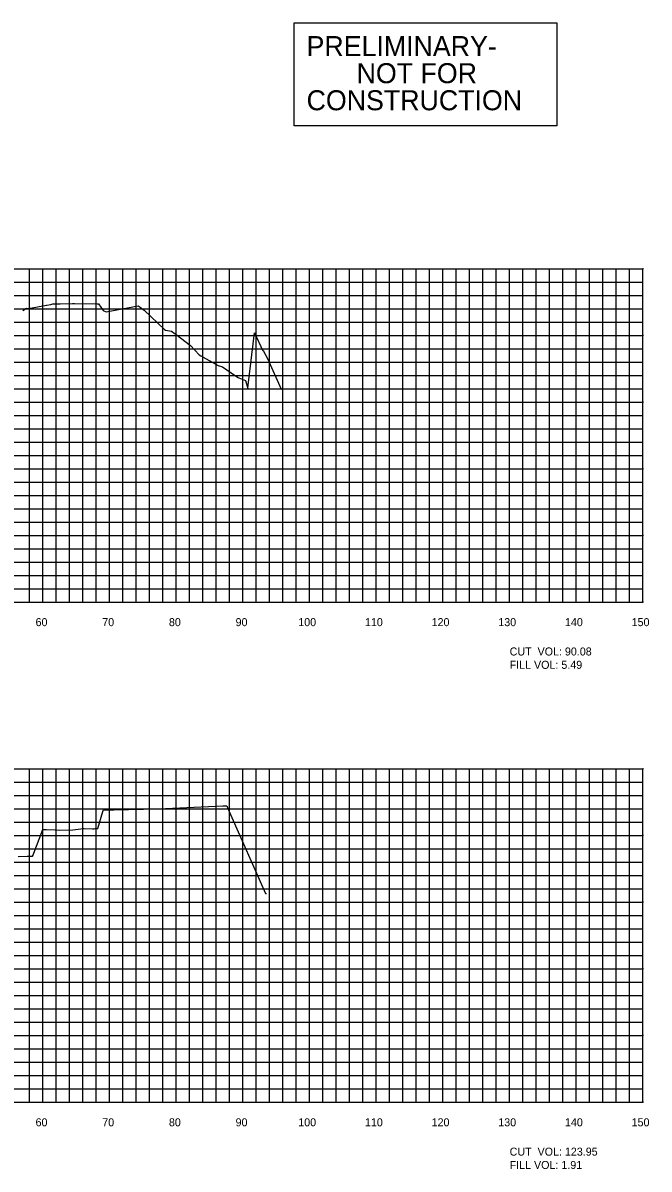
# Model space of a CAD drawing. Extents: x 1800880 to 1814006, y 250083 to 250560.
# Drawn here: x 1813568 to 1813661.9, y 250089.4 to 250261.3 of the extents above; entities that cross this region are included whole.
import ezdxf

# ---------------------------------------------------------------- set-up
doc = ezdxf.new("R2010")
doc.units = 0
for name, color, linetype in [('CL-CNST', 7, 'Continuous'), ('DESIGN - DRAINAGE - Bridges', 7, 'Continuous'), ('DRAINAGETXT', 7, 'Continuous'), ('Level 32', 7, 'Continuous'), ('Level 46', 7, 'Continuous')]:
    doc.layers.add(name, color=color, linetype=linetype)

msp = doc.modelspace()

# ---------------------------------------------------------------- linework, layer by layer
at = {"layer": 'CL-CNST'}
for points in [[(1813567.99, 250218.16), (1813568.52, 250218.53), (1813568.83, 250218.48), (1813571.52, 250218.96), (1813571.59, 250218.97), (1813572.13, 250219.04), (1813572.19, 250219.05), (1813572.5, 250219.14), (1813572.64, 250219.17), (1813572.67, 250219.17), (1813572.71, 250219.17), (1813573.05, 250219.17), (1813573.19, 250219.17), (1813573.61, 250219.18), (1813575.42, 250219.23), (1813575.72, 250219.23), (1813579.16, 250219.18), (1813579.32, 250219.18), (1813580.05, 250218.15), (1813580.48, 250217.94), (1813585.27, 250218.88), (1813585.61, 250218.64), (1813586.2, 250218.22), (1813589.23, 250215.33), (1813589.38, 250215.23), (1813590.29, 250215.04), (1813590.47, 250214.9), (1813590.63, 250214.79), (1813590.97, 250214.55), (1813593.14, 250212.93), (1813594.44, 250211.51), (1813594.68, 250211.36), (1813595.02, 250211.14), (1813597.27, 250209.91), (1813597.95, 250209.71), (1813599.87, 250208.39), (1813600.3, 250208.1), (1813600.38, 250208.05), (1813601.38, 250207.66), (1813601.64, 250206.84), (1813601.72, 250206.46), (1813601.8, 250206.96), (1813602.74, 250214.82), (1813603.99, 250212.11), (1813604.03, 250212.18), (1813604.7, 250210.98), (1813606.73, 250206.35), (1813607.05, 250206.41)], [(1813567.29, 250136.3), (1813568.62, 250136.36), (1813568.62, 250136.36), (1813568.63, 250136.36), (1813569.06, 250136.36), (1813569.43, 250136.36), (1813569.46, 250136.36), (1813569.52, 250136.5), (1813569.55, 250136.54), (1813569.64, 250136.8), (1813570.44, 250138.91), (1813570.99, 250140.35), (1813571.45, 250140.34), (1813571.53, 250140.34), (1813572.84, 250140.28), (1813573.56, 250140.25), (1813575.51, 250140.29), (1813577.08, 250140.49), (1813577.21, 250140.49), (1813578.46, 250140.46), (1813578.71, 250140.46), (1813578.82, 250140.47), (1813579.24, 250140.48), (1813580.01, 250143.02), (1813580.1, 250143.29), (1813580.34, 250143.29), (1813580.38, 250143.29), (1813580.63, 250143.29), (1813580.79, 250143.29), (1813580.96, 250143.29), (1813581.63, 250143.31), (1813588.28, 250143.44), (1813598.01, 250143.89), (1813598.41, 250143.89), (1813598.49, 250143.89), (1813598.61, 250143.89), (1813598.95, 250143.03), (1813604.37, 250130.73), (1813604.54, 250130.76)]]:
    msp.add_lwpolyline(points, dxfattribs=at)
at = {"layer": 'DESIGN - DRAINAGE - Bridges'}
for p, q in [((1813661, 250174.43), (1813661, 250224.43)), ((1813661.06, 250224.43), (1813661, 250224.43)), ((1813661.06, 250214.43), (1813661, 250214.43)), ((1813661.06, 250204.43), (1813661, 250204.43)), ((1813661.06, 250194.43), (1813661, 250194.43)), ((1813661.06, 250184.43), (1813661, 250184.43)), ((1813361, 250174.43), (1813661, 250174.43)), ((1813571, 250174.37), (1813571, 250174.43)), ((1813581, 250174.37), (1813581, 250174.43)), ((1813591, 250174.37), (1813591, 250174.43)), ((1813601, 250174.37), (1813601, 250174.43)), ((1813611, 250174.37), (1813611, 250174.43)), ((1813621, 250174.37), (1813621, 250174.43)), ((1813631, 250174.37), (1813631, 250174.43)), ((1813641, 250174.37), (1813641, 250174.43)), ((1813651, 250174.37), (1813651, 250174.43)), ((1813661, 250174.37), (1813661, 250174.43)), ((1813661.06, 250174.43), (1813661, 250174.43)), ((1813661, 250099.43), (1813661, 250149.43)), ((1813661.06, 250149.43), (1813661, 250149.43)), ((1813661.06, 250139.43), (1813661, 250139.43)), ((1813661.06, 250129.43), (1813661, 250129.43)), ((1813661.06, 250119.43), (1813661, 250119.43)), ((1813661.06, 250109.43), (1813661, 250109.43)), ((1813361, 250099.43), (1813661, 250099.43)), ((1813571, 250099.37), (1813571, 250099.43)), ((1813581, 250099.37), (1813581, 250099.43)), ((1813591, 250099.37), (1813591, 250099.43)), ((1813601, 250099.37), (1813601, 250099.43)), ((1813611, 250099.37), (1813611, 250099.43)), ((1813621, 250099.37), (1813621, 250099.43)), ((1813631, 250099.37), (1813631, 250099.43)), ((1813641, 250099.37), (1813641, 250099.43)), ((1813651, 250099.37), (1813651, 250099.43)), ((1813661, 250099.37), (1813661, 250099.43)), ((1813661.06, 250099.43), (1813661, 250099.43))]:
    msp.add_line(p, q, dxfattribs=at)
at = {"layer": 'Level 32'}
msp.add_lwpolyline([(1813608.68, 250261.29), (1813648.08, 250261.29), (1813648.08, 250245.85), (1813608.68, 250245.85)], close=True, dxfattribs=at)
at = {"layer": 'Level 46'}
for p, q in [((1813361, 250224.43), (1813661, 250224.43)), ((1813569, 250174.43), (1813569, 250224.43)), ((1813571, 250174.43), (1813571, 250224.43)), ((1813573, 250174.43), (1813573, 250224.43)), ((1813575, 250174.43), (1813575, 250224.43)), ((1813577, 250174.43), (1813577, 250224.43)), ((1813579, 250174.43), (1813579, 250224.43)), ((1813581, 250174.43), (1813581, 250224.43)), ((1813583, 250174.43), (1813583, 250224.43)), ((1813585, 250174.43), (1813585, 250224.43)), ((1813587, 250174.43), (1813587, 250224.43)), ((1813589, 250174.43), (1813589, 250224.43)), ((1813591, 250174.43), (1813591, 250224.43)), ((1813593, 250174.43), (1813593, 250224.43)), ((1813595, 250174.43), (1813595, 250224.43)), ((1813597, 250174.43), (1813597, 250224.43)), ((1813599, 250174.43), (1813599, 250224.43)), ((1813601, 250174.43), (1813601, 250224.43)), ((1813603, 250174.43), (1813603, 250224.43)), ((1813605, 250174.43), (1813605, 250224.43)), ((1813607, 250174.43), (1813607, 250224.43)), ((1813609, 250174.43), (1813609, 250224.43)), ((1813611, 250174.43), (1813611, 250224.43)), ((1813613, 250174.43), (1813613, 250224.43)), ((1813615, 250174.43), (1813615, 250224.43)), ((1813617, 250174.43), (1813617, 250224.43)), ((1813619, 250174.43), (1813619, 250224.43)), ((1813621, 250174.43), (1813621, 250224.43)), ((1813623, 250174.43), (1813623, 250224.43)), ((1813625, 250174.43), (1813625, 250224.43)), ((1813627, 250174.43), (1813627, 250224.43)), ((1813629, 250174.43), (1813629, 250224.43)), ((1813631, 250174.43), (1813631, 250224.43)), ((1813633, 250174.43), (1813633, 250224.43)), ((1813635, 250174.43), (1813635, 250224.43)), ((1813637, 250174.43), (1813637, 250224.43)), ((1813639, 250174.43), (1813639, 250224.43)), ((1813641, 250174.43), (1813641, 250224.43)), ((1813643, 250174.43), (1813643, 250224.43)), ((1813645, 250174.43), (1813645, 250224.43)), ((1813647, 250174.43), (1813647, 250224.43)), ((1813649, 250174.43), (1813649, 250224.43)), ((1813651, 250174.43), (1813651, 250224.43)), ((1813653, 250174.43), (1813653, 250224.43)), ((1813655, 250174.43), (1813655, 250224.43)), ((1813657, 250174.43), (1813657, 250224.43)), ((1813659, 250174.43), (1813659, 250224.43)), ((1813661, 250174.43), (1813661, 250224.43)), ((1813361, 250222.43), (1813661, 250222.43)), ((1813361, 250220.43), (1813661, 250220.43)), ((1813361, 250218.43), (1813661, 250218.43)), ((1813361, 250216.43), (1813661, 250216.43)), ((1813361, 250214.43), (1813661, 250214.43)), ((1813361, 250212.43), (1813661, 250212.43)), ((1813361, 250210.43), (1813661, 250210.43)), ((1813361, 250208.43), (1813661, 250208.43)), ((1813361, 250206.43), (1813661, 250206.43)), ((1813361, 250204.43), (1813661, 250204.43)), ((1813361, 250202.43), (1813661, 250202.43)), ((1813361, 250200.43), (1813661, 250200.43)), ((1813361, 250198.43), (1813661, 250198.43)), ((1813361, 250196.43), (1813661, 250196.43)), ((1813361, 250194.43), (1813661, 250194.43)), ((1813361, 250192.43), (1813661, 250192.43)), ((1813361, 250190.43), (1813661, 250190.43)), ((1813361, 250188.43), (1813661, 250188.43)), ((1813361, 250186.43), (1813661, 250186.43)), ((1813361, 250184.43), (1813661, 250184.43)), ((1813361, 250182.43), (1813661, 250182.43)), ((1813361, 250180.43), (1813661, 250180.43)), ((1813361, 250178.43), (1813661, 250178.43)), ((1813361, 250176.43), (1813661, 250176.43)), ((1813361, 250174.43), (1813661, 250174.43)), ((1813361, 250149.43), (1813661, 250149.43)), ((1813569, 250099.43), (1813569, 250149.43)), ((1813571, 250099.43), (1813571, 250149.43)), ((1813573, 250099.43), (1813573, 250149.43)), ((1813575, 250099.43), (1813575, 250149.43)), ((1813577, 250099.43), (1813577, 250149.43)), ((1813579, 250099.43), (1813579, 250149.43)), ((1813581, 250099.43), (1813581, 250149.43)), ((1813583, 250099.43), (1813583, 250149.43)), ((1813585, 250099.43), (1813585, 250149.43)), ((1813587, 250099.43), (1813587, 250149.43)), ((1813589, 250099.43), (1813589, 250149.43)), ((1813591, 250099.43), (1813591, 250149.43)), ((1813593, 250099.43), (1813593, 250149.43)), ((1813595, 250099.43), (1813595, 250149.43)), ((1813597, 250099.43), (1813597, 250149.43)), ((1813599, 250099.43), (1813599, 250149.43)), ((1813601, 250099.43), (1813601, 250149.43)), ((1813603, 250099.43), (1813603, 250149.43)), ((1813605, 250099.43), (1813605, 250149.43)), ((1813607, 250099.43), (1813607, 250149.43)), ((1813609, 250099.43), (1813609, 250149.43)), ((1813611, 250099.43), (1813611, 250149.43)), ((1813613, 250099.43), (1813613, 250149.43)), ((1813615, 250099.43), (1813615, 250149.43)), ((1813617, 250099.43), (1813617, 250149.43)), ((1813619, 250099.43), (1813619, 250149.43)), ((1813621, 250099.43), (1813621, 250149.43)), ((1813623, 250099.43), (1813623, 250149.43)), ((1813625, 250099.43), (1813625, 250149.43)), ((1813627, 250099.43), (1813627, 250149.43)), ((1813629, 250099.43), (1813629, 250149.43)), ((1813631, 250099.43), (1813631, 250149.43)), ((1813633, 250099.43), (1813633, 250149.43)), ((1813635, 250099.43), (1813635, 250149.43)), ((1813637, 250099.43), (1813637, 250149.43)), ((1813639, 250099.43), (1813639, 250149.43)), ((1813641, 250099.43), (1813641, 250149.43)), ((1813643, 250099.43), (1813643, 250149.43)), ((1813645, 250099.43), (1813645, 250149.43)), ((1813647, 250099.43), (1813647, 250149.43)), ((1813649, 250099.43), (1813649, 250149.43)), ((1813651, 250099.43), (1813651, 250149.43)), ((1813653, 250099.43), (1813653, 250149.43)), ((1813655, 250099.43), (1813655, 250149.43)), ((1813657, 250099.43), (1813657, 250149.43)), ((1813659, 250099.43), (1813659, 250149.43)), ((1813661, 250099.43), (1813661, 250149.43)), ((1813361, 250147.43), (1813661, 250147.43)), ((1813361, 250145.43), (1813661, 250145.43)), ((1813361, 250143.43), (1813661, 250143.43)), ((1813361, 250141.43), (1813661, 250141.43)), ((1813361, 250139.43), (1813661, 250139.43)), ((1813361, 250137.43), (1813661, 250137.43)), ((1813361, 250135.43), (1813661, 250135.43)), ((1813361, 250133.43), (1813661, 250133.43)), ((1813361, 250131.43), (1813661, 250131.43)), ((1813361, 250129.43), (1813661, 250129.43)), ((1813361, 250127.43), (1813661, 250127.43)), ((1813361, 250125.43), (1813661, 250125.43)), ((1813361, 250123.43), (1813661, 250123.43)), ((1813361, 250121.43), (1813661, 250121.43)), ((1813361, 250119.43), (1813661, 250119.43)), ((1813361, 250117.43), (1813661, 250117.43)), ((1813361, 250115.43), (1813661, 250115.43)), ((1813361, 250113.43), (1813661, 250113.43)), ((1813361, 250111.43), (1813661, 250111.43)), ((1813361, 250109.43), (1813661, 250109.43)), ((1813361, 250107.43), (1813661, 250107.43)), ((1813361, 250105.43), (1813661, 250105.43)), ((1813361, 250103.43), (1813661, 250103.43)), ((1813361, 250101.43), (1813661, 250101.43)), ((1813361, 250099.43), (1813661, 250099.43))]:
    msp.add_line(p, q, dxfattribs=at)

# ---------------------------------------------------------------- texts
for s, p in [('60', (1813569.9, 250170.83)), ('70', (1813579.9, 250170.83)), ('80', (1813589.9, 250170.83)), ('90', (1813599.9, 250170.83)), ('100', (1813609.3, 250170.83)), ('110', (1813619.3, 250170.83)), ('120', (1813629.3, 250170.83)), ('130', (1813639.3, 250170.83)), ('140', (1813649.3, 250170.83)), ('150', (1813659.3, 250170.83)), ('60', (1813569.9, 250095.83)), ('70', (1813579.9, 250095.83)), ('80', (1813589.9, 250095.83)), ('90', (1813599.9, 250095.83)), ('100', (1813609.3, 250095.83)), ('110', (1813619.3, 250095.83)), ('120', (1813629.3, 250095.83)), ('130', (1813639.3, 250095.83)), ('140', (1813649.3, 250095.83)), ('150', (1813659.3, 250095.83))]:
    msp.add_text(s, height=1.2).set_placement(p)
at = {"layer": 'DRAINAGETXT'}
for s, p in [('CUT  VOL: 90.08', (1813641, 250166.43)), ('FILL VOL: 5.49', (1813641, 250164.43)), ('CUT  VOL: 123.95', (1813641, 250091.43)), ('FILL VOL: 1.91', (1813641, 250089.43))]:
    msp.add_text(s, height=1.2, dxfattribs=at).set_placement(p)
at = {"layer": 'Level 32'}
for s, p in [('PRELIMINARY-', (1813610.54, 250256.31)), ('NOT FOR', (1813618.05, 250252.25)), ('CONSTRUCTION', (1813610.55, 250248.19))]:
    msp.add_text(s, height=3, dxfattribs=at).set_placement(p)

doc.saveas('drawing.dxf')
